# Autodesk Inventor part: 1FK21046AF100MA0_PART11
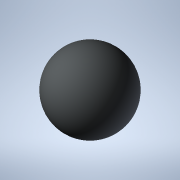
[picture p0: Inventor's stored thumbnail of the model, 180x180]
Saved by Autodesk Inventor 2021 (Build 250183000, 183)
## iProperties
Created: 2025-04
Part Number: 1FK21046AF100MA0_PART11
Material: Generic
Catalog Web Link: www.3dfindit.com
Description: -Servo synchronous motor
Document SubType Name: Modeling
Designer: psAdmin
Mass: 0.137258 g
Surface Area: 1.2868 cm^2
Volume: 0.137258 cm^3
Density: 1 g/cm^3
Appearance: PSOLRGB-212-217-219
Category: PARTsolutions
Title: 1FK21046AF100MA0_PART11
Author: Cadenas PARTsolutions
Comments: Servo synchronous motor
Sending System: PARTsolutions
Preprocessor: ST-DEVELOPER v19.3
PSOL_IDENT_0: {$CADENAS_DATA/23d-libs/siemens_ag/_cat_/4f/2b/1fk21046af100ma0.prj},216 {VTYP=3D},{NB=1FK21046AF100
PSOL_IDENT_1: MA0_PART11},{LINA=1FK21046AF100MA0_PART11},{NN=1FK21046AF100MA0_PART11},{NOPRJ=TRUE},{DATE=19.08.202
PSOL_IDENT_2: 5 14:00:37},{GEOMDATE=30.07.2025 02:01:06},{VERSION=},{LINEID=10},{WBVAR=},{WBNUMERIC=}  {NB=1FK2104
PSOL_IDENT_3: 6AF100MA0_PART11},{LINA=1FK21046AF100MA0_PART11},{KT=DUMMY},{PREVIEW=../../../_pool_/cb/72/p_d211_xx
PSOL_IDENT_4: _00434j.png},{DESCSHORT=SIMOTICS S-1FK2 HD, SINAMICS S210 3AC 400V-480V, 3.2 Nm, 3000 rpm},{DESCLONG=
PSOL_IDENT_5: SIMOTICS S-1FK2 HD servo motor M0=3.2 Nm; PN = 1 kW at nN=3000 rpm (380-480 V); PN = 0.5 kW at nN=15
PSOL_IDENT_6: 00 rpm (200-240 V); with holding brake; degree of protection IP64; cylindrical shaft D19x40mm; absol
PSOL_IDENT_7: ute encoder 22-bit + 12-bit multiturn (encoder AM22DQC); with OCC interface; plug size M17, rotatabl
PSOL_IDENT_8: e; SIMOTICS S-1FK2 servomotorfor a wide range of uses in industrial environments. SIMOTICS S‑1FK2 se
PSOL_IDENT_9: rvomotors are compact synchronous motors with a high dynamic performance that set themselves apart a
PSOL_IDENT_10: s a result of their high power density, degree of protection and overload capability. The motors are
PSOL_IDENT_11: available in two variants: as High Dynamic variant (highest dynamic performance as a result of the
PSOL_IDENT_12: low intrinsic moment of inertia for applications demanding a high dynamic performance with low moved
PSOL_IDENT_13: masses) - and as Compact variant (precise and stable closed-loop control for medium up to large mov
PSOL_IDENT_14: ed masses as a result of a medium intrinsic moment of inertia). SIMOTICSS‑1FK2 servomotors fully exp
PSOL_IDENT_15: loit their strengths in a system with the SINAMICSS210 frequency converter and simple connection usi
PSOL_IDENT_16: ng the one cable connection (OCC). Advantages include the short control and positioning times, fast
PSOL_IDENT_17: and precise correction of disturbing quantities as well as stable control with a high dynamic perfor
PSOL_IDENT_18: mance. The servo motors can be configured to address a wide range of requirements. For example with
PSOL_IDENT_19: and without holding brake, IP64 or IP65 degree of protection, singleturn or multiturn absolute encod
PSOL_IDENT_20: ers - to name just a few. Further, the servomotors are available in different shaft heights extendin
PSOL_IDENT_21: g from 20 to 100. A shaft sealing ring is available to achieve an IP65 degree of protection and for
PSOL_IDENT_22: subsequent mounting at the motor or as spare part. SIMOTICS - the optimum motor for each and every m
PSOL_IDENT_23: otion control application.},{INTNO=195125049673},{SUPPLIERALTNO=1FK2104-6AF10-0MA0},{MANUID=1FK21046
PSOL_IDENT_24: AF100MA0},{MANUNAME=Siemens},{MANUTYPEDESC=Synchronous motor 1FK2-HD 3.2 NM},{AAU732=SIMOTICS},{AAO0
PSOL_IDENT_25: 57=S-1FK2},{AAU734=SIMOTICS S-1FK2 HD servo motor M0=3.2 Nm; PN = 1 kW at nN=3000 rpm (380-480 V); P
PSOL_IDENT_26: N = 0.5 kW at nN=1500 rpm (200-240 V); with holding brake; degree of protection IP64; cylindrical sh
PSOL_IDENT_27: aft D19x40mm; absolute encoder 22-bit + 12-bit multiturn (encoder AM22DQC); with OCC interface; plug
PSOL_IDENT_28: size M17, rotatable;},{AAW338=Synchronous motor 1FK2-HD 3.2 NM},{AAO742=SIMOTICS},{AAO663=404294869
PSOL_IDENT_29: 4534},{NOCUPEROU=1},{PRICEQUANTITY=1},{QUANTITYMIN=1},{QUANTITYINT=1},{CTN=85015220},{COO=DE},{AAO67
PSOL_IDENT_30: 6=1FK2104-6AF10-0MA0},{AAO677=Siemens AG},{ORDERUNIT=C62},{CONTENTUNIT=C62}
NB: 1FK21046AF100MA0_PART11
NT: Servo synchronous motor
NBSYN: $MANUID._PART11
LINA: 1FK21046AF100MA0_PART11
CATALOG: SIEMENS
PREVIEW: ../../../_pool_/cb/72/p_d211_xx_00434j.png
DESCSHORT: SIMOTICS S-1FK2 HD, SINAMICS S210 3AC 400V-480V, 3.2 Nm, 3000 rpm
DESCLONG: SIMOTICS S-1FK2 HD servo motor M0=3.2 Nm; PN = 1 kW at nN=3000 rpm (380-480 V); PN = 0.5 kW at nN=1500 rpm (200-240 V); with holding brake; degree of protection
INTNO: 195125049673
SUPPLIERALTNO: 1FK2104-6AF10-0MA0
MANUID: 1FK21046AF100MA0
MANUNAME: Siemens
MANUTYPEDESC: Synchronous motor 1FK2-HD 3.2 NM
AAU732: SIMOTICS
AAO057: S-1FK2
AAU734: SIMOTICS S-1FK2 HD servo motor M0=3.2 Nm; PN = 1 kW at nN=3000 rpm (380-480 V); PN = 0.5 kW at nN=1500 rpm (200-240 V); with holding brake; degree of protection
AAW338: Synchronous motor 1FK2-HD 3.2 NM
AAO742: SIMOTICS
AAO663: 4042948694534.0
NOCUPEROU: 1
PRICEQUANTITY: 1
QUANTITYMIN: 1
QUANTITYINT: 1
CTN: 85015220
COO: DE
ARTICLENO: 1FK21046AF100MA0_PART11
BOMINFO: 1FK21046AF100MA0_PART11
CREATOR: CADENAS GmbH
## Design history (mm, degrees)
feature "2025_04_17_14_59_39_0177"
body "Solid1"
